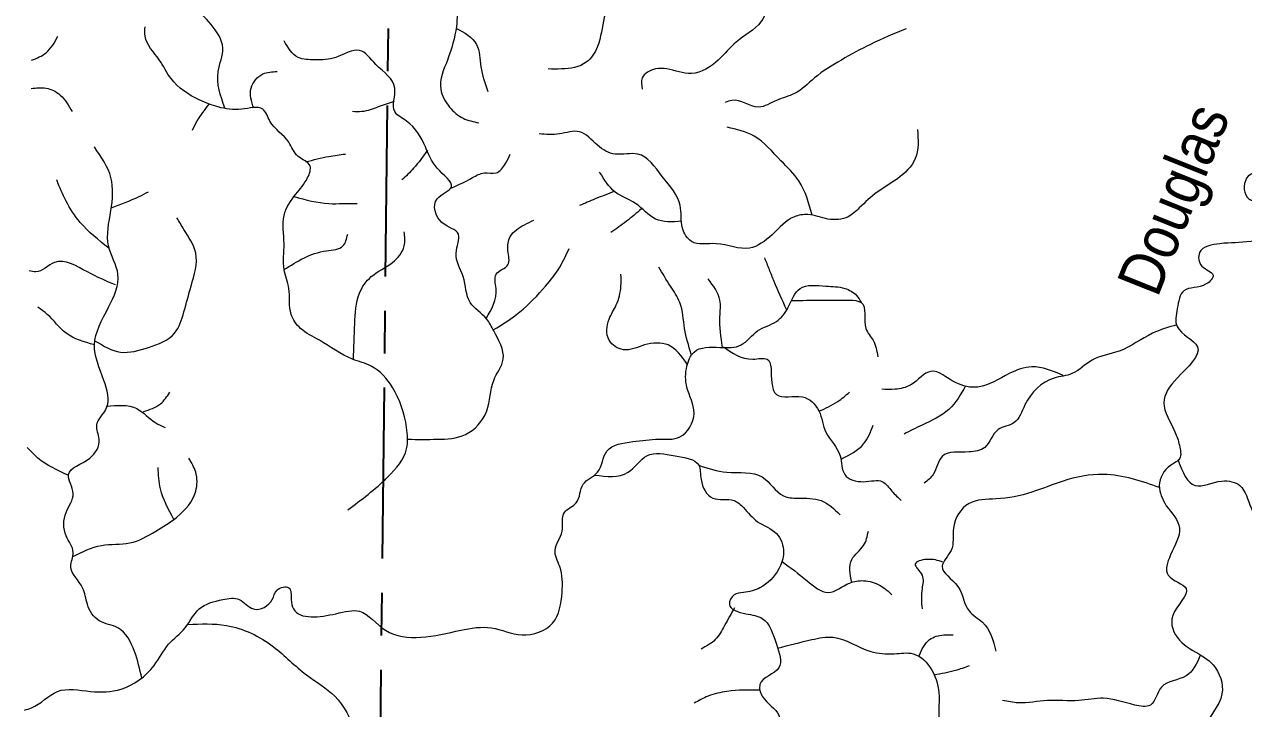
# Model space of a CAD drawing. Extents: x 796677 to 815278, y 8501144 to 8534586.
# Drawn here: x 796983 to 800404, y 8530556 to 8532477 of the extents above; entities that cross this region are included whole.
import ezdxf

# ---------------------------------------------------------------- set-up
doc = ezdxf.new("R2010")
doc.units = 0
doc.header["$LTSCALE"] = 80
doc.linetypes.add('LONG_DASH_SHORT_DASH', pattern=[9.9, 6, -1.2, 1.5, -1.2])
doc.layers.add('15', color=7, linetype='Continuous', lineweight=13)
doc.layers.add('62', color=7, linetype='LONG_DASH_SHORT_DASH', lineweight=35)

msp = doc.modelspace()

# ---------------------------------------------------------------- linework, layer by layer
at = {"layer": '15'}
for points in [[(801614.24, 8534367.61), (801612.36, 8534320.62), (801637.49, 8534270.33), (801675.18, 8534226.32), (801700.31, 8534163.46), (801687.74, 8534119.46), (801650.05, 8534075.46), (801562.11, 8534062.89), (801480.45, 8534018.88), (801417.63, 8533962.31), (801398.79, 8533912.02), (801342.25, 8533886.87), (801248.03, 8533861.73), (801191.49, 8533811.44), (801178.93, 8533786.3), (801134.96, 8533798.87), (801116.11, 8533742.29), (801053.3, 8533710.86), (801009.32, 8533698.29), (800971.63, 8533666.86), (800990.48, 8533635.43), (801015.61, 8533635.43), (801053.3, 8533616.57), (801078.42, 8533660.57), (801103.55, 8533635.43), (801116.11, 8533578.85), (801134.96, 8533541.14), (801116.11, 8533522.28), (801090.99, 8533465.7), (801040.73, 8533446.84), (800977.92, 8533471.99), (800933.94, 8533453.13), (800915.1, 8533396.56), (800883.69, 8533377.7), (800908.82, 8533327.41), (800852.28, 8533302.26), (800795.75, 8533314.84), (800776.9, 8533283.41), (800802.03, 8533245.69), (800789.47, 8533207.97), (800764.34, 8533176.54), (800770.62, 8533119.97), (800776.9, 8533069.68), (800795.75, 8533038.25), (800852.28, 8533013.1), (800852.28, 8532956.53), (800858.56, 8532874.81), (800833.44, 8532843.38), (800827.16, 8532799.37), (800802.03, 8532761.66), (800739.21, 8532686.22), (800726.65, 8532598.22), (800732.93, 8532529.07), (800770.62, 8532478.78), (800802.03, 8532453.64), (800802.03, 8532415.92), (800764.34, 8532390.78), (800707.81, 8532365.63), (800663.83, 8532403.35), (800613.58, 8532390.78), (800569.61, 8532353.06), (800513.07, 8532340.49), (800475.38, 8532277.63), (800481.67, 8532177.05), (800481.67, 8532126.76), (800462.82, 8532076.47), (800412.57, 8532045.04), (800418.85, 8531987.2), (800450.26, 8531987.2), (800487.95, 8532006.06), (800494.23, 8531980.92), (800469.1, 8531924.34), (800469.1, 8531886.62), (800425.13, 8531867.77), (800337.19, 8531861.48), (800280.65, 8531836.33), (800286.93, 8531798.62), (800318.34, 8531773.47), (800299.5, 8531748.33), (800236.68, 8531729.47), (800217.84, 8531679.18), (800217.84, 8531628.89), (800274.37, 8531572.32), (800217.84, 8531484.31), (800180.15, 8531415.16), (800211.55, 8531333.44), (800224.12, 8531295.73), (800224.12, 8531258.01), (800198.99, 8531239.15), (800167.58, 8531182.58), (800186.43, 8531126)], [(798726.71, 8532807.58), (798653.7, 8532728.96), (798628.57, 8532653.53), (798628.57, 8532578.1), (798609.73, 8532496.38), (798590.88, 8532414.66), (798559.47, 8532370.65), (798490.37, 8532351.8), (798452.68, 8532351.8)], [(799212.76, 8532653.53), (799131.1, 8532640.96), (799074.57, 8532546.67), (799049.44, 8532483.8), (798980.34, 8532427.23), (798930.09, 8532376.94), (798854.71, 8532339.22), (798785.61, 8532351.8), (798754.2, 8532351.8), (798716.51, 8532326.65), (798716.51, 8532295.22)], [(798174.57, 8532629.42), (798195.14, 8532540.38), (798195.14, 8532471.23), (798170.01, 8532376.94), (798151.17, 8532295.22), (798176.29, 8532244.93), (798213.98, 8532213.5), (798257.95, 8532200.93)], [(797545.36, 8532242.67), (797526.6, 8532344.57), (797539.82, 8532410.73), (797506.77, 8532476.89), (797453.88, 8532529.81)], [(797003.25, 8532376.18), (797044.02, 8532397.48), (797077.07, 8532443.79)], [(797890.19, 8531114.03), (798002.57, 8531206.65), (798055.46, 8531286.04), (798055.46, 8531345.58), (798015.79, 8531458.05), (797956.3, 8531517.59), (797903.41, 8531537.44), (797810.86, 8531590.37), (797757.97, 8531623.44), (797731.53, 8531663.14), (797724.92, 8531735.91), (797711.7, 8531788.84), (797711.7, 8531861.61), (797711.7, 8531941), (797744.75, 8532000.55), (797777.81, 8532046.86), (797784.42, 8532079.94), (797751.36, 8532106.4), (797724.92, 8532146.09), (797672.03, 8532205.64), (797652.2, 8532238.72), (797592.7, 8532238.72), (797526.6, 8532245.33), (797473.71, 8532265.18), (797394.38, 8532324.72), (797361.33, 8532377.65), (797321.66, 8532443.81), (797321.66, 8532470.27)], [(798194.08, 8532466.69), (798251.67, 8532420.94), (798264.24, 8532358.08), (798283.08, 8532288.93)], [(799457.75, 8532464.95), (799357.24, 8532420.94), (799275.58, 8532376.94), (799200.2, 8532326.65), (799143.67, 8532282.65), (799093.41, 8532263.79), (799043.16, 8532244.93), (798967.78, 8532263.79), (798948.93, 8532257.5)], [(798059.5, 8531312.43), (798141.4, 8531312.5), (798220.73, 8531325.73), (798280.22, 8531391.89), (798300.06, 8531477.9), (798326.5, 8531537.44), (798300.06, 8531616.83), (798280.22, 8531649.91), (798233.95, 8531696.22), (798214.12, 8531768.99), (798194.28, 8531835.15), (798200.89, 8531888.08), (798154.62, 8531921.16), (798141.4, 8531987.32), (798181.06, 8532020.39), (798141.4, 8532073.32), (798108.34, 8532132.86), (798055.46, 8532205.64), (798022.4, 8532232.1), (798022.4, 8532298.26), (797969.52, 8532364.42), (797923.24, 8532404.11), (797857.13, 8532384.26), (797797.64, 8532377.65), (797751.36, 8532384.26), (797711.7, 8532430.58)], [(797626.12, 8532241.57), (797619.15, 8532298.26), (797652.2, 8532337.95), (797691.87, 8532344.57)], [(797002.37, 8532296.97), (797044.02, 8532298.25), (797083.68, 8532278.4), (797116.74, 8532232.09)], [(797500.47, 8532252.75), (797467.1, 8532205.64), (797453.88, 8532179.17)], [(798020.82, 8532260.69), (797976.13, 8532245.33), (797929.85, 8532232.1), (797903.41, 8532232.1)], [(799489.16, 8532182.07), (799482.87, 8532100.35), (799432.62, 8532043.78), (799376.09, 8532006.06), (799325.83, 8531962.06), (799294.43, 8531936.91), (799237.89, 8531930.63), (799181.36, 8531943.2), (799143.67, 8531936.91), (799080.85, 8531886.62), (799018.03, 8531848.91), (798923.81, 8531861.48), (798854.71, 8531867.76), (798829.58, 8531905.48), (798823.3, 8531968.34), (798773.05, 8532050.06), (798703.95, 8532112.92), (798641.13, 8532112.92), (798590.88, 8532138.07), (798540.63, 8532175.78), (798484.09, 8532169.5), (798427.56, 8532169.5)], [(799193.53, 8531941.42), (799156.23, 8532037.49), (799105.98, 8532094.06), (799030.6, 8532163.21), (798955.22, 8532188.36)], [(797312.63, 8530642.27), (797291.92, 8530717.07), (797245.64, 8530783.23), (797192.76, 8530803.08), (797159.7, 8530849.39), (797146.48, 8530895.7), (797113.43, 8530955.24), (797120.04, 8530994.94), (797100.21, 8531041.25), (797100.21, 8531107.41), (797120.04, 8531160.33), (797106.82, 8531213.26), (797166.31, 8531259.57), (797192.76, 8531312.5), (797186.14, 8531352.19), (797212.59, 8531398.5), (797205.98, 8531477.89), (797179.53, 8531577.13), (797219.2, 8531682.98), (797245.64, 8531775.6), (797219.2, 8531854.99), (797225.81, 8531954.23), (797225.81, 8532046.85), (797179.53, 8532132.86)], [(797772.48, 8532091.1), (797837.3, 8532106.4), (797883.58, 8532113.02)], [(798113.75, 8532123.73), (798075.29, 8532073.32), (798042.24, 8532040.24)], [(798181.92, 8532017.97), (798240.56, 8532046.86), (798273.61, 8532060.09), (798306.67, 8532060.09), (798333.11, 8532086.55), (798346.33, 8532113.02)], [(797219.49, 8531849.25), (797139.87, 8531921.15), (797100.21, 8531980.7), (797073.76, 8532040.24)], [(798826.77, 8531924.28), (798754.2, 8531930.63), (798697.67, 8531974.63), (798641.13, 8532006.06), (798597.16, 8532062.63)], [(797226.33, 8531962.03), (797305.14, 8531993.93), (797331.58, 8532007.16)], [(798639.45, 8532008.23), (798584.6, 8531987.2), (798540.63, 8531968.34)], [(797740.09, 8531993.76), (797837.3, 8531974.08), (797876.97, 8531974.08), (797916.63, 8531974.08)], [(797181.95, 8531588.25), (797252.25, 8531557.28), (797331.58, 8531570.51), (797404.3, 8531610.21), (797430.74, 8531669.75), (797450.57, 8531742.53), (797463.8, 8531835.15), (797430.74, 8531901.31), (797410.91, 8531934.38)], [(798714.64, 8531959.31), (798672.54, 8531924.34), (798628.57, 8531892.91)], [(797906.03, 8531536.06), (797910.02, 8531636.68), (797923.24, 8531722.68), (797956.3, 8531768.99), (798015.79, 8531808.69), (798048.85, 8531855), (798048.85, 8531894.69)], [(798278.87, 8531651.73), (798306.67, 8531735.91), (798306.67, 8531775.61), (798339.72, 8531802.07), (798339.72, 8531841.77), (798346.33, 8531881.46), (798385.99, 8531914.54), (798412.44, 8531927.77)], [(797711.7, 8531788.84), (797830.69, 8531841.77), (797876.97, 8531855), (797890.19, 8531888.08)], [(798298.77, 8531619.35), (798372.77, 8531669.76), (798445.49, 8531742.53), (798485.16, 8531795.46), (798511.6, 8531848.38)], [(797238.75, 8531745.65), (797159.7, 8531782.22), (797067.15, 8531808.68), (797014.27, 8531782.22), (796996.68, 8531785.06)], [(798854.31, 8531551.65), (798835.53, 8531623.44), (798822.3, 8531696.22), (798795.86, 8531742.53), (798762.81, 8531795.46)], [(799121.67, 8531676.68), (799086.73, 8531755.76), (799073.51, 8531788.84), (799060.29, 8531821.92)], [(798842.98, 8531522.95), (798789.25, 8531577.13), (798723.14, 8531577.13), (798663.65, 8531563.9), (798623.98, 8531590.37), (798623.98, 8531649.91), (798643.81, 8531689.6), (798657.04, 8531742.53), (798657.04, 8531775.61)], [(798941.87, 8531571.38), (798934.69, 8531656.52), (798934.69, 8531702.83), (798901.63, 8531762.38)], [(796982.97, 8530552.37), (797003.03, 8530558.3), (797075.74, 8530604.61), (797168.29, 8530604.61), (797254.23, 8530611.22), (797346.78, 8530677.38), (797387.77, 8530736.92), (797434.05, 8530783.24), (797473.71, 8530836.16), (797539.82, 8530862.63), (797586.09, 8530862.63), (797625.76, 8530836.16), (797678.64, 8530862.63), (797691.87, 8530889.09), (797724.92, 8530895.7), (797731.53, 8530862.63), (797738.14, 8530836.16), (797857.13, 8530822.93), (797923.24, 8530829.55), (797995.96, 8530776.62), (798095.12, 8530756.77), (798207.5, 8530776.62), (798293.44, 8530783.24), (798379.38, 8530763.39), (798465.32, 8530796.47), (798491.77, 8530882.47), (798485.16, 8530955.25), (798471.93, 8531001.56), (798491.77, 8531054.48), (798498.38, 8531107.41), (798531.43, 8531133.87), (798551.26, 8531186.8), (798590.93, 8531219.88), (798617.37, 8531279.42), (798690.09, 8531305.89), (798762.81, 8531312.5), (798822.3, 8531319.12), (798861.97, 8531385.28), (798842.14, 8531458.05), (798842.14, 8531517.59), (798861.97, 8531557.29), (798934.69, 8531570.52), (798994.18, 8531577.13), (799040.46, 8531616.83), (799093.35, 8531643.29), (799126.4, 8531682.99), (799159.45, 8531735.91), (799232.17, 8531742.53), (799285.06, 8531735.91), (799318.11, 8531716.07), (799331.33, 8531696.22)], [(799136.31, 8531701.85), (799218.95, 8531702.83), (799271.84, 8531702.83), (799298.28, 8531702.83), (799331.33, 8531696.22), (799344.55, 8531623.44), (799364.39, 8531590.37), (799377.61, 8531544.05)], [(797179.65, 8531577.8), (797100.21, 8531610.21), (797047.32, 8531663.14), (797020.88, 8531682.98)], [(800217.08, 8531633.88), (800148.74, 8531610.03), (800054.51, 8531559.75), (799979.13, 8531534.6), (799922.6, 8531496.88), (799872.35, 8531484.31), (799790.69, 8531408.88), (799759.28, 8531358.59), (799715.31, 8531339.73), (799677.62, 8531289.44), (799633.64, 8531276.87), (799558.26, 8531264.3), (799533.14, 8531214.01), (799508.01, 8531188.86)], [(798944.9, 8531571.66), (799027.24, 8531537.44), (799066.9, 8531537.44), (799080.12, 8531471.28), (799093.35, 8531438.2), (799166.06, 8531431.59), (799212.34, 8531391.89), (799232.17, 8531332.35), (799271.84, 8531266.19), (799285.06, 8531213.26), (799337.94, 8531193.42), (799390.83, 8531193.42), (799417.27, 8531166.95), (799443.71, 8531140.49)], [(799898.15, 8531491.2), (799809.53, 8531515.74), (799746.71, 8531496.88), (799658.77, 8531459.17), (799595.95, 8531471.74), (799526.86, 8531503.17), (799470.32, 8531465.45), (799426.35, 8531452.88), (799388.66, 8531452.88)], [(799623.98, 8531462.61), (799577.11, 8531396.31), (799501.73, 8531352.3), (799451.48, 8531327.16)], [(797316.95, 8531390.18), (797364.64, 8531411.73), (797391.08, 8531444.81)], [(799212.66, 8531391.32), (799265.22, 8531418.35), (799298.28, 8531444.82)], [(797212.76, 8531405.35), (797298.53, 8531398.5), (797351.41, 8531358.81), (797377.86, 8531345.58)], [(799274.87, 8531256.72), (799337.94, 8531299.27), (799364.39, 8531352.2)], [(797106.21, 8531211.67), (797020.88, 8531259.57), (796991.17, 8531289.47)], [(797118.95, 8530983.25), (797199.37, 8531014.78), (797278.7, 8531021.4), (797351.41, 8531054.48), (797410.91, 8531094.17), (797463.8, 8531166.95), (797463.8, 8531219.88), (797443.96, 8531259.57)], [(798582.73, 8531212.07), (798676.87, 8531219.88), (798729.75, 8531266.19), (798809.08, 8531266.19), (798875.19, 8531239.73), (798881.8, 8531200.03), (798914.85, 8531147.11), (798974.35, 8531140.49), (799000.79, 8531120.64), (799040.46, 8531080.95), (799093.35, 8531047.87), (799113.18, 8530994.94), (799099.96, 8530948.63), (799047.07, 8530895.7), (799000.79, 8530882.47), (798974.35, 8530875.86), (798961.13, 8530849.39), (799007.41, 8530822.93), (799053.68, 8530809.7), (799093.35, 8530736.92), (799099.96, 8530670.77), (799047.07, 8530624.46), (799053.68, 8530591.38), (799099.96, 8530538.45), (799080.12, 8530445.83), (799086.73, 8530339.98), (799146.23, 8530253.97), (799192.51, 8530201.04), (799225.56, 8530161.35), (799205.73, 8530108.42), (799205.73, 8530068.73), (799258.61, 8530048.88), (799278.45, 8530015.8), (799265.22, 8529956.26), (799331.33, 8529903.33), (799384.22, 8529863.64), (799410.66, 8529797.48), (799410.66, 8529731.32)], [(800220.11, 8531252.74), (800268.09, 8531182.58), (800343.47, 8531195.15), (800393.72, 8531182.58), (800425.13, 8531119.72), (800487.95, 8531056.86), (800557.05, 8531031.71), (800557.05, 8530962.56), (800506.79, 8530918.56), (800519.36, 8530836.84), (800544.48, 8530767.69), (800544.48, 8530704.83), (800594.74, 8530673.4), (800613.58, 8530629.4), (800613.58, 8530566.54)], [(797402.73, 8531087.64), (797364.64, 8531173.56), (797358.02, 8531233.11)], [(798875.19, 8531239.73), (798954.52, 8531219.88), (799053.68, 8531206.65), (799113.18, 8531153.72), (799152.84, 8531147.11), (799218.95, 8531140.49), (799271.84, 8531100.79)], [(800167.91, 8531177.01), (800092.2, 8531201.44), (800010.54, 8531214.01), (799897.47, 8531195.15), (799809.53, 8531163.72), (799709.02, 8531144.86), (799633.64, 8531132.29), (799589.67, 8531063.14), (799583.39, 8531000.28), (799558.26, 8530956.28), (799602.24, 8530899.7), (799633.64, 8530830.55), (799671.33, 8530799.12), (799709.02, 8530717.4)], [(800186.43, 8531126), (800224.12, 8531063.14), (800198.99, 8530987.71), (800192.71, 8530931.13), (800242.96, 8530893.42), (800205.27, 8530817.98), (800224.12, 8530748.83), (800286.93, 8530704.83), (800318.34, 8530679.69), (800343.47, 8530597.97), (800293.22, 8530497.39), (800299.5, 8530409.38), (800337.19, 8530277.38), (800343.47, 8530183.08), (800381.16, 8530088.79), (800368.6, 8530019.64), (800362.31, 8529963.07), (800312.06, 8529868.78), (800242.96, 8529812.2), (800173.87, 8529761.91), (800148.74, 8529667.62), (800161.3, 8529585.9), (800198.99, 8529523.04), (800236.68, 8529466.46), (800236.68, 8529422.46), (800192.71, 8529391.03), (800161.3, 8529378.46)], [(799304.49, 8530910.51), (799304.89, 8530975.09), (799337.94, 8531014.79), (799351.16, 8531054.48)], [(799560.38, 8530967.66), (799514.29, 8530975.14), (799482.88, 8530962.56), (799501.73, 8530931.13), (799501.73, 8530893.42), (799501.73, 8530836.84)], [(799109.43, 8530969.25), (799179.28, 8530915.55), (799238.78, 8530882.47), (799298.28, 8530908.94), (799337.94, 8530915.55), (799384.22, 8530902.32), (799417.27, 8530875.86)], [(798975.19, 8530839.13), (798947.91, 8530789.85), (798921.47, 8530750.16), (798881.8, 8530723.69)], [(797441.63, 8530792.59), (797549.74, 8530789.84), (797681.95, 8530730.29), (797774.5, 8530650.9), (797853.83, 8530591.36), (797913.33, 8530492.12), (797966.21, 8530386.27), (798085.21, 8530287.03), (798164.54, 8530240.72), (798237.25, 8530121.64), (798316.58, 8530029.02), (798362.86, 8529943.01), (798376.08, 8529876.85), (798428.97, 8529790.85), (798468.63, 8529632.07), (798574.4, 8529532.83), (798700.01, 8529453.44), (798792.56, 8529413.74), (798944.6, 8529433.59), (799063.6, 8529499.75), (799149.54, 8529585.76), (799182.59, 8529638.68), (799182.59, 8529744.54), (799182.59, 8529823.93), (799169.37, 8529870.24)], [(799096.7, 8530726.01), (799192.51, 8530750.16), (799252, 8530756.77), (799357.78, 8530717.08), (799423.88, 8530710.46), (799476.77, 8530710.46), (799529.65, 8530664.15), (799549.49, 8530591.38), (799549.49, 8530525.22), (799562.71, 8530465.68), (799582.54, 8530406.13)], [(799493.4, 8530704.64), (799523.04, 8530750.16), (799562.71, 8530763.39), (799589.15, 8530763.39)], [(800283.45, 8530707.39), (800242.96, 8530648.26), (800173.87, 8530616.83), (800142.46, 8530566.54), (800098.49, 8530566.54), (800010.54, 8530585.4), (799941.44, 8530579.11), (799853.5, 8530579.11), (799771.84, 8530572.82), (799727.87, 8530579.11)], [(799535.73, 8530651.62), (799595.76, 8530664.15), (799635.43, 8530677.38)], [(799047.79, 8530608.67), (798954.52, 8530604.61), (798901.63, 8530591.38), (798861.97, 8530571.53)]]:
    msp.add_spline(points, degree=3, dxfattribs=at)
at = {"layer": '62'}
msp.add_lwpolyline([(798016.61, 8533572.26), (814284.25, 8533388.27), (814262.81, 8531543), (808840.42, 8531605.49), (808819.33, 8529760.28), (810626.64, 8529739.55), (810605.4, 8527894.32), (806991.04, 8527935.71), (807012.04, 8529780.9), (805204.77, 8529801.39), (805225.62, 8531646.54), (803418.25, 8531666.89), (803356, 8526131.49), (801549.03, 8526151.78), (801424.6, 8515081.06), (799618.4, 8515101.38), (799514.64, 8505875.84), (801320.21, 8505855.41), (801278.28, 8502165.14), (799472.96, 8502185.61), (799493.81, 8504030.73), (797688.38, 8504051.06), (798016.61, 8533572.26)], close=True, dxfattribs=at)

# ---------------------------------------------------------------- texts
at = {"layer": '15', "width": 0.9}
msp.add_text('Douglas', height=125, rotation=68.214, dxfattribs=at).set_placement((800162.35, 8531707.51))

doc.saveas('drawing.dxf')
